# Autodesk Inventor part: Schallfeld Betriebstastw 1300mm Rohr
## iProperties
Shininess: 20.0
Length Units: 11269
Angle Units: 11279
Time Units: 11290
Mass Units: 11283
Length Display Precision: 2
Angle Display Precision: 2
Part Number: Schallfeld Betriebstastw 1300mm Rohr
Material: Lexan (klar)
Document SubType Name: Modellieren
Description: Schallfeld 1,3 m
Checked By: Alves
Created: 2005-08
Designer: Klein
Manufacturer: Standard
Standards Organization: Custom
Density: 0.0
Volumn: 0.0
Area: 0.0
PropertySet Name: Model Information
Control State: 0
Master: False
Checked Out: False
Last Check In By: Kramp
Last Check In Date: 2005-08-11
ME: ST
Title: Schallfelder
Author: Klein
Comments: keine Bemerkung
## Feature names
1. Innenglocke [Revolution]
